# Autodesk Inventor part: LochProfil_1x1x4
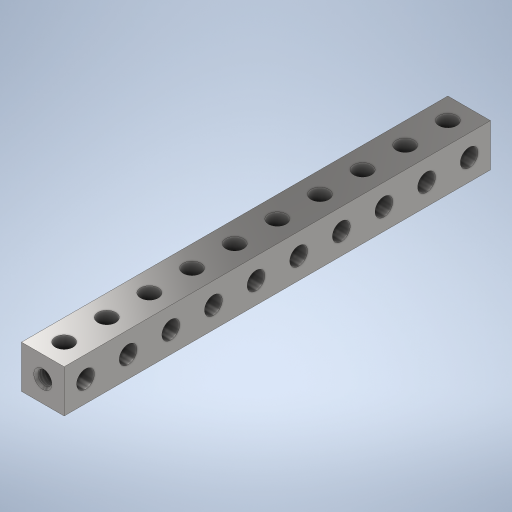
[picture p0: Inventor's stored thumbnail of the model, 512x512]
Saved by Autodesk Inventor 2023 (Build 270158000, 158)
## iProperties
Created: 2023-11
Part Number: LochProfil_1x1x4
Material: Edelstahl
Document SubType Name: Modeling
Designer: Greiner
Density: 8 g/cm^3
Appearance: Halbpoliert
Radius: 2,075 mm
Einheitsmaß: 10,000 mm
Author: Greiner
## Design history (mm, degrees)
sketch "Skizze1"
  geometry: L1 (5, 50)-(-5, 50); L2 (-5, 50)-(-5, -50); L3 (-5, -50)-(5, -50); L4 (5, -50)-(5, 50); 3 further points
  constraints: 8 end point, 2 midpoint, 2 parallel, 1 horizontal, 1 horizontal alignment, 1 perpendicular, 1 vertical alignment
  dimensions: "d0" = 100 distance of L3.end L1.start (computed from Löcher, Einheitsmaß); "d1" = 10 distance of L1.start L1.end (= Einheitsmaß)
extrude "Extrusion1" new body sketch "Skizze1" stored distance "d2" = 10 (= Einheitsmaß); taper "d3" = 0 deg
sketch "Skizze2"
  geometry: C1 r 2.075 at (0, -45); 1 further point
  constraints: 1 centre point, 1 vertical alignment
  dimensions: "d4" = 4.15 diameter of C1 (= 2 x Radius); "d5" = 45 distance of point (0, 0) C1.centre (computed from Löcher, Einheitsmaß)
sketch "Skizze4"
  geometry: C1 r 2.075 at (-95, 5); 1 further point
  constraints: 1 centre point, 1 horizontal alignment
  dimensions: "d6" = 4.15 diameter of C1 (= 2 x Radius); "d7" = 45 distance of point (-50, 5) C1.centre (computed from Löcher, Einheitsmaß)
extrude "Extrusion2" cut sketch "Skizze2" distance "d8" = 10 (= Einheitsmaß); taper "d9" = 0 deg
extrude "Extrusion3" cut sketch "Skizze4" distance "d10" = 10 (= Einheitsmaß); taper "d11" = 0 deg
pattern_linear "Rechteckige Anordnung1" dims "d14" = 10 (= Einheitsmaß)
sketch "Skizze5"
  geometry: 2 further points
  constraints: 1 coincident
hole "Bohrung1" sketch "Skizze5" at (5, -5) diameter "d15" = 3.242; stored, may be unused: countersink angle "d19" = 90 deg, drill point angle "d21" = 118 deg; dims "d16" = 5 (= 0.5 x Einheitsmaß), "d17" = 4, "d18" = 2, "d20" = 10.8 (computed from Einheitsmaß)
mirror "Spiegeln1"
chamfer "Fase2" distance "d25" = 0.5 (= Fasen); stored, may be unused: second distance "d26" = 2, angle "d27" = 45 deg
node "Volumenkörper1"
other parameters: "Einheitsmaß" = 10 [user parameter; used in 10 equation terms], "Radius" = 2.075 [user parameter; used in 2 equation terms], "Fasen" = 0.5 [user parameter; used in 1 equation term]
